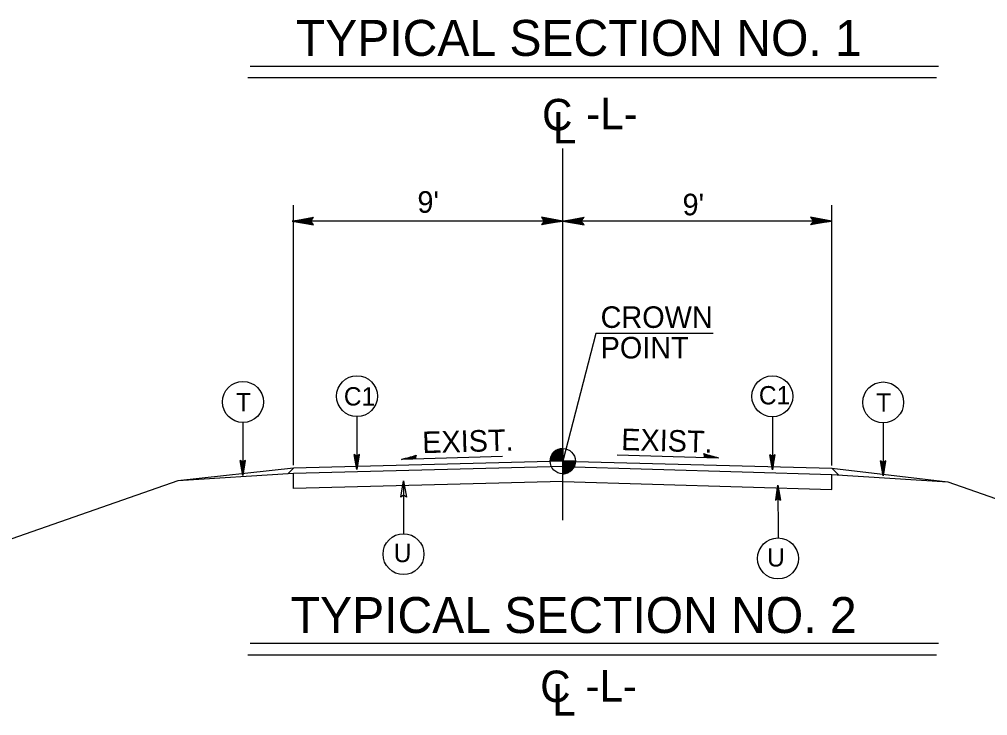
# Model space of a CAD drawing. Extents: x 55823 to 57507, y 47399 to 48499.
# Drawn here: x 56414.9 to 56749.5, y 47646 to 47886.3 of the extents above; entities that cross this region are included whole.
import ezdxf

# ---------------------------------------------------------------- set-up
doc = ezdxf.new("R2010")
doc.units = 0
for name, color, linetype in [('Old_Level_1', 7, 'Continuous'), ('Old_Level_11', 7, 'Continuous'), ('Old_Level_2', 7, 'Continuous'), ('Old_Level_20', 7, 'Continuous'), ('Old_Level_3', 7, 'Continuous')]:
    doc.layers.add(name, color=color, linetype=linetype)

msp = doc.modelspace()

# ---------------------------------------------------------------- linework, layer by layer
at = {"layer": 'Old_Level_1'}
for p, q in [((56494.71, 47870.19), (56732.54, 47870.19)), ((56493.93, 47866.26), (56731.75, 47866.26)), ((56602.67, 47713.49), (56602.67, 47841.8)), ((56509.67, 47732.48), (56509.67, 47822.23)), ((56695.67, 47732.37), (56695.67, 47822.23)), ((56509.24, 47816.72), (56516.61, 47818.02)), ((56509.24, 47816.72), (56516.47, 47817.84)), ((56516.33, 47817.65), (56509.24, 47816.72)), ((56509.24, 47816.72), (56516.2, 47817.46)), ((56516.06, 47817.28), (56509.24, 47816.72)), ((56509.24, 47816.72), (56515.93, 47817.09)), ((56515.79, 47816.91), (56509.24, 47816.72)), ((56509.24, 47816.72), (56516.61, 47815.42)), ((56516.47, 47815.61), (56509.24, 47816.72)), ((56509.24, 47816.72), (56516.33, 47815.79)), ((56516.2, 47815.98), (56509.24, 47816.72)), ((56509.24, 47816.72), (56516.06, 47816.17)), ((56515.93, 47816.35), (56509.24, 47816.72)), ((56509.24, 47816.72), (56515.79, 47816.53)), ((56515.65, 47816.72), (56509.24, 47816.72)), ((56602.67, 47816.71), (56509.67, 47816.71)), ((56515.65, 47816.72), (56516.61, 47818.02)), ((56516.61, 47815.42), (56515.65, 47816.72)), ((56602.67, 47816.71), (56595.3, 47818.01)), ((56595.3, 47818.01), (56596.26, 47816.71)), ((56602.67, 47816.71), (56595.3, 47815.41)), ((56596.26, 47816.71), (56595.3, 47815.41)), ((56595.44, 47817.83), (56602.67, 47816.71)), ((56602.67, 47816.71), (56595.44, 47815.6)), ((56602.67, 47816.71), (56595.58, 47817.64)), ((56595.58, 47815.79), (56602.67, 47816.71)), ((56595.71, 47817.46), (56602.67, 47816.71)), ((56602.67, 47816.71), (56595.71, 47815.97)), ((56602.67, 47816.71), (56595.85, 47817.27)), ((56595.85, 47816.16), (56602.67, 47816.71)), ((56595.98, 47817.09), (56602.67, 47816.71)), ((56602.67, 47816.71), (56595.98, 47816.34)), ((56602.67, 47816.71), (56596.12, 47816.9)), ((56596.12, 47816.53), (56602.67, 47816.71)), ((56596.26, 47816.71), (56602.67, 47816.71)), ((56602.67, 47816.71), (56610.04, 47818.02)), ((56602.67, 47816.71), (56609.9, 47817.83)), ((56609.76, 47817.64), (56602.67, 47816.71)), ((56602.67, 47816.71), (56609.63, 47817.46)), ((56609.49, 47817.27), (56602.67, 47816.71)), ((56602.67, 47816.71), (56609.36, 47817.09)), ((56609.22, 47816.9), (56602.67, 47816.71)), ((56602.67, 47816.71), (56610.04, 47815.41)), ((56609.9, 47815.6), (56602.67, 47816.71)), ((56602.67, 47816.71), (56609.76, 47815.79)), ((56609.63, 47815.97), (56602.67, 47816.71)), ((56602.67, 47816.71), (56609.49, 47816.16)), ((56609.36, 47816.34), (56602.67, 47816.71)), ((56602.67, 47816.71), (56609.22, 47816.53)), ((56609.08, 47816.71), (56602.67, 47816.71)), ((56695.67, 47816.71), (56602.67, 47816.71)), ((56609.08, 47816.71), (56610.04, 47818.02)), ((56610.04, 47815.41), (56609.08, 47816.71)), ((56695.67, 47816.71), (56688.3, 47818.01)), ((56688.3, 47818.01), (56689.26, 47816.71)), ((56695.67, 47816.71), (56688.3, 47815.41)), ((56689.26, 47816.71), (56688.3, 47815.41)), ((56688.44, 47817.83), (56695.67, 47816.71)), ((56695.67, 47816.71), (56688.44, 47815.6)), ((56695.67, 47816.71), (56688.58, 47817.64)), ((56688.58, 47815.79), (56695.67, 47816.71)), ((56688.71, 47817.46), (56695.67, 47816.71)), ((56695.67, 47816.71), (56688.71, 47815.97)), ((56695.67, 47816.71), (56688.85, 47817.27)), ((56688.85, 47816.16), (56695.67, 47816.71)), ((56688.98, 47817.09), (56695.67, 47816.71)), ((56695.67, 47816.71), (56688.98, 47816.34)), ((56695.67, 47816.71), (56689.12, 47816.9)), ((56689.12, 47816.53), (56695.67, 47816.71)), ((56689.26, 47816.71), (56695.67, 47816.71)), ((56531.58, 47730.92), (56530.66, 47736.11)), ((56531.58, 47735.43), (56530.66, 47736.11)), ((56531.58, 47730.92), (56530.79, 47736.01)), ((56530.93, 47735.91), (56531.58, 47730.92)), ((56531.58, 47730.92), (56531.06, 47735.82)), ((56531.19, 47735.72), (56531.58, 47730.92)), ((56531.58, 47730.92), (56531.32, 47735.63)), ((56531.45, 47735.53), (56531.58, 47730.92)), ((56531.58, 47730.92), (56532.49, 47736.11)), ((56532.49, 47736.11), (56531.58, 47735.43)), ((56532.36, 47736.01), (56531.58, 47730.92)), ((56531.58, 47730.92), (56532.23, 47735.91)), ((56532.1, 47735.82), (56531.58, 47730.92)), ((56531.58, 47730.92), (56531.97, 47735.72)), ((56531.84, 47735.63), (56531.58, 47730.92)), ((56531.58, 47730.92), (56531.71, 47735.53)), ((56531.58, 47735.43), (56531.58, 47730.92)), ((56581.88, 47735.42), (56546.98, 47734.45)), ((56551.62, 47735.04), (56549.01, 47734.9)), ((56551.63, 47735.13), (56549.75, 47735.06)), ((56551.63, 47735.26), (56550.28, 47735.22)), ((56550.81, 47735.37), (56551.67, 47735.41)), ((56551.73, 47735.5), (56551.24, 47735.51)), ((56551.78, 47735.63), (56551.71, 47735.63)), ((56551.86, 47735.73), (56551.82, 47735.69)), ((56602.67, 47738.21), (56602.67, 47733.84)), ((56621.53, 47736), (56656.43, 47735.03)), ((56651.55, 47736.32), (56651.59, 47736.27)), ((56651.63, 47736.21), (56651.7, 47736.21)), ((56651.68, 47736.08), (56652.16, 47736.1)), ((56652.6, 47735.95), (56651.74, 47735.99)), ((56651.77, 47735.71), (56653.66, 47735.65)), ((56651.78, 47735.85), (56653.13, 47735.81)), ((56651.78, 47735.53), (56654.72, 47735.39)), ((56651.78, 47735.32), (56655.59, 47735.17)), ((56651.79, 47735.63), (56654.4, 47735.48)), ((56651.79, 47735.23), (56655.96, 47735.09)), ((56651.81, 47735.42), (56655.18, 47735.29)), ((56675.09, 47730.87), (56674.18, 47736.05)), ((56675.09, 47735.38), (56674.18, 47736.05)), ((56675.09, 47730.87), (56674.31, 47735.95)), ((56674.44, 47735.85), (56675.09, 47730.87)), ((56675.09, 47730.87), (56674.57, 47735.76)), ((56674.7, 47735.66), (56675.09, 47730.87)), ((56675.09, 47730.87), (56674.83, 47735.57)), ((56674.96, 47735.47), (56675.09, 47730.87)), ((56675.09, 47730.87), (56676.01, 47736.05)), ((56676.01, 47736.05), (56675.09, 47735.38)), ((56675.88, 47735.95), (56675.09, 47730.87)), ((56675.09, 47730.87), (56675.75, 47735.85)), ((56675.62, 47735.76), (56675.09, 47730.87)), ((56675.09, 47730.87), (56675.48, 47735.66)), ((56675.36, 47735.57), (56675.09, 47730.87)), ((56675.09, 47730.87), (56675.23, 47735.47)), ((56675.09, 47735.38), (56675.09, 47730.87)), ((56492.19, 47728.93), (56491.27, 47734.11)), ((56492.19, 47733.44), (56491.27, 47734.11)), ((56492.19, 47728.93), (56491.4, 47734.02)), ((56491.53, 47733.92), (56492.19, 47728.93)), ((56492.19, 47728.93), (56491.66, 47733.82)), ((56491.79, 47733.73), (56492.19, 47728.93)), ((56492.19, 47728.93), (56491.92, 47733.63)), ((56492.05, 47733.54), (56492.19, 47728.93)), ((56492.19, 47728.93), (56493.1, 47734.11)), ((56493.1, 47734.11), (56492.19, 47733.44)), ((56492.97, 47734.02), (56492.19, 47728.93)), ((56492.19, 47728.93), (56492.84, 47733.92)), ((56492.71, 47733.82), (56492.19, 47728.93)), ((56492.19, 47728.93), (56492.58, 47733.73)), ((56492.45, 47733.63), (56492.19, 47728.93)), ((56492.19, 47728.93), (56492.32, 47733.54)), ((56492.19, 47733.44), (56492.19, 47728.93)), ((56602.67, 47733.84), (56509.67, 47731.43)), ((56602.67, 47732.01), (56509.67, 47729.59)), ((56551.62, 47734.65), (56547.45, 47734.5)), ((56551.63, 47734.74), (56547.82, 47734.59)), ((56551.6, 47734.84), (56548.23, 47734.7)), ((56551.62, 47734.94), (56548.69, 47734.8)), ((56602.67, 47733.84), (56598.31, 47733.84)), ((56607.03, 47733.84), (56602.67, 47733.84)), ((56602.67, 47729.48), (56602.67, 47733.84)), ((56602.67, 47733.84), (56607.03, 47733.84)), ((56602.67, 47733.84), (56695.67, 47731.42)), ((56602.67, 47732.01), (56695.67, 47729.26)), ((56713.39, 47728.77), (56712.47, 47733.95)), ((56713.39, 47733.28), (56712.47, 47733.95)), ((56713.39, 47728.77), (56712.6, 47733.86)), ((56712.74, 47733.76), (56713.39, 47728.77)), ((56713.39, 47728.77), (56712.87, 47733.66)), ((56713, 47733.57), (56713.39, 47728.77)), ((56713.39, 47728.77), (56713.13, 47733.47)), ((56713.26, 47733.38), (56713.39, 47728.77)), ((56713.39, 47728.77), (56714.3, 47733.95)), ((56714.3, 47733.95), (56713.39, 47733.28)), ((56714.17, 47733.86), (56713.39, 47728.77)), ((56713.39, 47728.77), (56714.04, 47733.76)), ((56713.91, 47733.66), (56713.39, 47728.77)), ((56713.39, 47728.77), (56713.78, 47733.57)), ((56713.65, 47733.47), (56713.39, 47728.77)), ((56713.39, 47728.77), (56713.52, 47733.38)), ((56713.39, 47733.28), (56713.39, 47728.77)), ((56509.67, 47731.43), (56469.67, 47727)), ((56509.67, 47729.59), (56469.67, 47727)), ((56507.71, 47729.46), (56509.67, 47731.43)), ((56509.67, 47724.4), (56509.67, 47729.59)), ((56697.99, 47729.11), (56695.67, 47731.42)), ((56695.67, 47731.42), (56735.67, 47726.67)), ((56695.67, 47724.07), (56695.67, 47729.26)), ((56695.67, 47729.26), (56735.67, 47726.67)), ((56469.67, 47727), (56326.08, 47677.05)), ((56602.67, 47726.81), (56509.67, 47724.39)), ((56602.67, 47726.81), (56695.67, 47724.07)), ((56677.04, 47725.57), (56676.13, 47720.39)), ((56676.26, 47720.49), (56677.04, 47725.57)), ((56677.04, 47725.57), (56676.39, 47720.58)), ((56676.52, 47720.68), (56677.04, 47725.57)), ((56677.04, 47725.57), (56676.65, 47720.77)), ((56676.78, 47720.87), (56677.04, 47725.57)), ((56677.04, 47725.57), (56676.91, 47720.96)), ((56677.04, 47725.57), (56677.96, 47720.39)), ((56677.04, 47721.06), (56677.04, 47725.57)), ((56677.18, 47720.96), (56677.04, 47725.57)), ((56677.04, 47725.57), (56677.31, 47720.87)), ((56677.44, 47720.77), (56677.04, 47725.57)), ((56677.04, 47725.57), (56677.57, 47720.68)), ((56677.7, 47720.58), (56677.04, 47725.57)), ((56677.04, 47725.57), (56677.83, 47720.49)), ((56735.67, 47726.67), (56813.86, 47699.47)), ((56676.13, 47720.39), (56677.04, 47721.06)), ((56677.04, 47721.06), (56677.96, 47720.39)), ((56494.71, 47670.95), (56732.54, 47670.95)), ((56493.93, 47667.02), (56731.75, 47667.02))]:
    msp.add_line(p, q, dxfattribs=at)
for points in [[(56654.67, 47777.93), (56614.08, 47777.93), (56602.67, 47733.84)], [(56598.47, 47735.02), (56602.67, 47735.02)], [(56598.49, 47735.11), (56602.67, 47735.11)], [(56598.52, 47735.2), (56602.67, 47735.2)], [(56598.55, 47735.28), (56602.67, 47735.28)], [(56598.58, 47735.37), (56602.67, 47735.37)], [(56598.62, 47735.46), (56602.67, 47735.46)], [(56598.65, 47735.54), (56602.67, 47735.54)], [(56598.69, 47735.63), (56602.67, 47735.63)], [(56598.73, 47735.72), (56602.67, 47735.72)], [(56598.77, 47735.81), (56602.67, 47735.81)], [(56598.82, 47735.89), (56602.67, 47735.89)], [(56598.87, 47735.98), (56602.67, 47735.98)], [(56598.92, 47736.07), (56602.67, 47736.07)], [(56598.97, 47736.16), (56602.67, 47736.15)], [(56599.03, 47736.24), (56602.67, 47736.24)], [(56599.08, 47736.33), (56602.67, 47736.33)], [(56599.15, 47736.42), (56602.67, 47736.42)], [(56599.21, 47736.5), (56602.67, 47736.5)], [(56599.28, 47736.59), (56602.67, 47736.59)], [(56599.35, 47736.68), (56602.67, 47736.68)], [(56599.43, 47736.77), (56602.67, 47736.77)], [(56599.51, 47736.85), (56602.67, 47736.85)], [(56599.6, 47736.94), (56602.67, 47736.94)], [(56599.69, 47737.03), (56602.67, 47737.03)], [(56599.78, 47737.12), (56602.67, 47737.11)], [(56599.89, 47737.2), (56602.67, 47737.2)], [(56599.99, 47737.29), (56602.67, 47737.29)], [(56600.11, 47737.38), (56602.67, 47737.38)], [(56600.24, 47737.46), (56602.67, 47737.46)], [(56600.37, 47737.55), (56602.67, 47737.55)], [(56600.52, 47737.64), (56602.67, 47737.64)], [(56600.68, 47737.73), (56602.67, 47737.73)], [(56600.86, 47737.81), (56602.67, 47737.81)], [(56601.06, 47737.9), (56602.67, 47737.9)], [(56601.31, 47737.99), (56602.67, 47737.99)], [(56601.61, 47738.07), (56602.67, 47738.07)], [(56602.05, 47738.16), (56602.67, 47738.16)], [(56598.31, 47734.06), (56602.67, 47734.06)], [(56598.31, 47733.97), (56602.67, 47733.97)], [(56598.31, 47733.89), (56598.31, 47733.89), (56602.67, 47733.89)], [(56598.32, 47734.24), (56602.67, 47734.23)], [(56598.32, 47734.15), (56602.67, 47734.15)], [(56598.33, 47734.32), (56602.67, 47734.32)], [(56598.34, 47734.41), (56602.67, 47734.41)], [(56598.36, 47734.5), (56602.67, 47734.5)], [(56598.37, 47734.58), (56602.67, 47734.58)], [(56598.39, 47734.67), (56602.67, 47734.67)], [(56598.4, 47734.76), (56602.67, 47734.76)], [(56598.42, 47734.85), (56602.67, 47734.85)], [(56598.45, 47734.93), (56602.67, 47734.93)], [(56602.67, 47733.78), (56607.03, 47733.78), (56607.03, 47733.78)], [(56602.67, 47733.69), (56607.03, 47733.69)], [(56602.67, 47733.61), (56607.02, 47733.61)], [(56602.67, 47733.52), (56607.02, 47733.52)], [(56602.67, 47733.43), (56607.01, 47733.43)], [(56602.67, 47733.35), (56607, 47733.34)], [(56602.67, 47733.26), (56606.99, 47733.26)], [(56602.67, 47733.17), (56606.98, 47733.17)], [(56602.67, 47733.08), (56606.96, 47733.08)], [(56602.67, 47733), (56606.95, 47733)], [(56602.67, 47732.91), (56606.93, 47732.91)], [(56602.67, 47732.82), (56606.91, 47732.82)], [(56602.67, 47732.73), (56606.89, 47732.73)], [(56602.67, 47732.65), (56606.86, 47732.65)], [(56602.67, 47732.56), (56606.84, 47732.56)], [(56602.67, 47732.47), (56606.81, 47732.47)], [(56602.67, 47732.39), (56606.78, 47732.39)], [(56602.67, 47732.3), (56606.75, 47732.3)], [(56602.67, 47732.21), (56606.72, 47732.21)], [(56602.67, 47732.12), (56606.68, 47732.12)], [(56602.67, 47732.04), (56606.64, 47732.04)], [(56602.67, 47731.95), (56606.6, 47731.95)], [(56602.67, 47731.86), (56606.56, 47731.86)], [(56602.67, 47731.77), (56606.51, 47731.77)], [(56602.67, 47731.69), (56606.46, 47731.69)], [(56602.67, 47731.6), (56606.41, 47731.6)], [(56602.67, 47731.51), (56606.36, 47731.51)], [(56602.67, 47731.43), (56606.3, 47731.43)], [(56602.67, 47731.34), (56606.24, 47731.34)], [(56602.67, 47731.25), (56606.18, 47731.25)], [(56602.67, 47731.16), (56606.11, 47731.16)], [(56602.67, 47731.08), (56606.04, 47731.08)], [(56602.67, 47730.99), (56605.97, 47730.99)], [(56602.67, 47730.9), (56605.89, 47730.9)], [(56602.67, 47730.81), (56605.81, 47730.81)], [(56602.67, 47730.73), (56605.72, 47730.73)], [(56602.67, 47730.64), (56605.63, 47730.64)], [(56602.67, 47730.55), (56605.53, 47730.55)], [(56602.67, 47730.47), (56605.43, 47730.47)], [(56602.67, 47730.38), (56605.32, 47730.38)], [(56602.67, 47730.29), (56605.2, 47730.29)], [(56602.67, 47730.2), (56605.07, 47730.2)], [(56602.67, 47730.12), (56604.94, 47730.12)], [(56602.67, 47730.03), (56604.79, 47730.03)], [(56602.67, 47729.94), (56604.62, 47729.94)], [(56602.67, 47729.85), (56604.44, 47729.85)], [(56602.67, 47729.77), (56604.23, 47729.77)], [(56602.67, 47729.68), (56603.97, 47729.68)], [(56602.67, 47729.59), (56603.66, 47729.59)], [(56602.67, 47729.5), (56603.14, 47729.5)]]:
    msp.add_lwpolyline(points, dxfattribs=at)
msp.add_circle((56602.67, 47733.84), 4.36, dxfattribs=at)
for centre, radius, start, end in [((56535.81, 47784.44), 51.22, 282.5916, 288.4254), ((56554.37, 47734.8), 2.6, 156.2047, 184.1523), ((56602.67, 47733.84), 4.36, 89.9905, 179.9905), ((56667.6, 47785.02), 51.22, 251.5746, 257.4084), ((56649.04, 47735.39), 2.6, 355.8477, 23.7953), ((56602.67, 47733.84), 4.36, 269.9905, 359.9905)]:
    msp.add_arc(centre, radius, start, end, dxfattribs=at)
at = {"layer": 'Old_Level_11'}
msp.add_lwpolyline([(56546.72, 47721.37), (56547.65, 47727.06), (56548.68, 47721.37), (56547.65, 47722.09)], close=True, dxfattribs=at)
at = {"layer": 'Old_Level_2'}
for p, q in [((56531.58, 47749.19), (56531.58, 47730.92)), ((56675.09, 47749.13), (56675.09, 47730.87)), ((56492.19, 47747.2), (56492.19, 47728.93)), ((56713.39, 47747.04), (56713.39, 47728.77)), ((56547.65, 47727.06), (56547.65, 47708.79)), ((56677.04, 47725.57), (56677.05, 47707.3))]:
    msp.add_line(p, q, dxfattribs=at)
for centre in [(56531.58, 47756.26), (56675.09, 47756.2), (56492.19, 47754.27), (56713.39, 47754.11), (56547.65, 47701.72), (56677.04, 47700.23)]:
    msp.add_circle(centre, 7.07, dxfattribs=at)

# ---------------------------------------------------------------- texts
at = {"layer": 'Old_Level_1'}
for s, height, p in [('TYPICAL SECTION NO. 1', 12.4114, (56510.48, 47873.74)), ("9'", 7.447, (56552.47, 47819.58)), ("9'", 7.447, (56644.07, 47818.7)), ('CROWN', 7.447, (56615.76, 47779.83)), ('POINT', 7.447, (56615.76, 47769.28)), ('TYPICAL SECTION NO. 2', 12.4114, (56508.7, 47674.5))]:
    msp.add_text(s, height=height, dxfattribs=at).set_placement(p)
for rotation, p in [(358.3467, (56622.81, 47737.66)), (1.5917, (56554.24, 47736.57))]:
    msp.add_text('EXIST.', height=7.447, rotation=rotation, dxfattribs=at).set_placement(p)
at = {"layer": 'Old_Level_20'}
for s, height, p in [('C1', 6.327, (56527.05, 47753.04)), ('C1', 6.327, (56670.44, 47753.42)), ('T', 6.33, (56489.77, 47751.05)), ('T', 6.33, (56710.98, 47750.89)), ('U', 6.33, (56544.27, 47698.97)), ('U', 6.33, (56673.28, 47697.45))]:
    msp.add_text(s, height=height, dxfattribs=at).set_placement(p)
at = {"layer": 'Old_Level_3'}
for s, p in [('C    ', (56595.54, 47848.03)), ('-L-', (56610.8, 47848.41)), ('L', (56599.3, 47843.54)), ('C', (56594.9, 47650.67)), ('-L-', (56610.55, 47650.85)), ('L', (56599.05, 47645.98))]:
    msp.add_text(s, height=10.86, dxfattribs=at).set_placement(p)

doc.saveas('drawing.dxf')
